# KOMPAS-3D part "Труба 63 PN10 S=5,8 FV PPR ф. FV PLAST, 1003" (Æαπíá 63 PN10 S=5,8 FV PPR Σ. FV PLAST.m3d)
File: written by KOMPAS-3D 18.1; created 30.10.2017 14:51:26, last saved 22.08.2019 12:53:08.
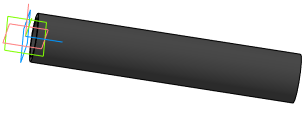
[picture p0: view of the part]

Document properties: Автор: Милов; Организация: Милов; Полное имя файла: D:\1 ПКИ 3D\Полипропиленовые фитинги, трубы\Трубы\Труба 63 PN10 S=5,8 FV PPR ф. FV PLAST.m3d

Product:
- Part/product: Труба 63 PN10 S=5,8 FV PPR ф. FV PLAST  | designation 1003
    Материал: Полипропилен  ГОСТ 26996-86 (density 900 kg/m3)
    Масса: 0.152669
    Раздел спецификации: Прочие изделия
    Примечание: м
- Part/product: Труба 63 PN10 S=5,8 FV PPR ф. FV PLAST  | designation 1002
    Материал: Полипропилен  ГОСТ 26996-86 (density 900 kg/m3)
    Масса: 0.152669
    Раздел спецификации: Прочие изделия
    Примечание: м
- Part/product: Труба 63 PN10 S=5,8 ПВХ  | designation 4
    Материал: Полипропилен  ГОСТ 26996-86 (density 900 kg/m3)
    Масса: 0.326673
    Раздел спецификации: Прочие изделия
    Примечание: м
- Part/product: Труба 63 PN10 S=5,8 FV PPR ф. FV PLAST  | designation 1000
    Материал: Полипропилен  ГОСТ 26996-86 (density 900 kg/m3)
    Масса: 0.864543
    Раздел спецификации: Прочие изделия
    Примечание: м
- Part/product: Труба 63 PN10 S=5,8 FV PPR ф. FV PLAST
    Материал: Полипропилен  ГОСТ 26996-86 (density 900 kg/m3)
    Масса: 0.152669
    Раздел спецификации: Прочие изделия
    Примечание: м
- Part/product: Труба ф63х5.8 (PN10) FV PPR ф. FV PLAST  | designation 01 (с поворотом напр.)
    Материал: Полипропилен  ГОСТ 26996-86 (density 900 kg/m3)
    Масса: 0.132262
- Part/product: Труба 63 PN10 S=5,8 FV PPR ф. FV PLAST  | designation 01
    Материал: Полипропилен  ГОСТ 26996-86 (density 900 kg/m3)
    Масса: 0.129218
    Раздел спецификации: Прочие изделия
    Примечание: м
- Part/product: Труба 63 PN10 S=5,8 FV PPR ф. FV PLAST  | designation 02
    Материал: Полипропилен  ГОСТ 26996-86 (density 900 kg/m3)
    Масса: 0.129218
    Раздел спецификации: Прочие изделия
    Примечание: м
- Part/product: Труба 63 PN10 S=5,8  | designation ПВХ
    Материал: Полипропилен  ГОСТ 26996-86 (density 900 kg/m3)
    Масса: 0.113272
    Раздел спецификации: Прочие изделия
    Примечание: м
- Part/product: Труба 63 PN10 S=5,8 ПВХ  | designation 1
    Материал: Полипропилен  ГОСТ 26996-86 (density 900 kg/m3)
    Масса: 0.0640683
    Раздел спецификации: Прочие изделия
    Примечание: м
  - Body: Тело 1
      Масса: 0.0800148
- Part/product: Труба 63 PN10 S=5,8 ПВХ  | designation 2
    Материал: Полипропилен  ГОСТ 26996-86 (density 900 kg/m3)
    Раздел спецификации: Прочие изделия
    Примечание: м
- Part/product: Труба 63 PN10 S=5,8 ПВХ  | designation 3
    Материал: Полипропилен  ГОСТ 26996-86 (density 900 kg/m3)
    Масса: 0.059608
    Раздел спецификации: Прочие изделия
    Примечание: м
- Part/product: Труба 63 PN10 S=5,8 ПВХ  | designation 5
    Материал: Полипропилен  ГОСТ 26996-86 (density 900 kg/m3)
    Масса: 0.129218
    Раздел спецификации: Прочие изделия
    Примечание: м
- Part/product: Труба 63 PN10 S=5,8 FV PPR ф. FV PLAST  | designation 1001
    Материал: Полипропилен  ГОСТ 26996-86 (density 900 kg/m3)
    Масса: 0.294541
    Раздел спецификации: Прочие изделия
    Примечание: м
- Part/product: Труба 63 PN10 S=5,8 FV PPR ф. FV PLAST  | designation М32колено
    Материал: Полипропилен  ГОСТ 26996-86 (density 900 kg/m3)
    Масса: 0.051404
    Раздел спецификации: Прочие изделия
    Примечание: м

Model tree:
1. Эскиз:1
2. Операция выдавливания:1  (with: Вырезать элемент выдавливания:8)  (labels: Полипропилен  ГОСТ 26996-86; L + 34.0)
3. Элемент выдавливания:1  (with: Операция выдавливания:1)  (labels: Полипропилен  ГОСТ 26996-86)
     Расстояние 2 = 34
4. Элемент выдавливания:2  (with: Операция выдавливания:1)
     Расстояние 2 = 30
5. Элемент выдавливания:5  (with: Операция выдавливания:1)
     Расстояние 1 = 10
6. Элемент выдавливания:6  (with: Элемент выдавливания:5)
     Расстояние 1 = 568
7. Эскиз:5  (with: Элемент выдавливания:6, Элемент выдавливания:2)  (labels: FV PPR Редукция 32х20 AA209032020; Труба 63 PN10 S=5,8 FV PPR ф. FV PLAST; FV PPR Вварное седло 63х32)
8. Элемент выдавливания:9  (labels: Полипропилен  ГОСТ 26996-86; L+32.755)
     Расстояние 2 = 91
9. Элемент выдавливания:10  (with: Операция выдавливания:1)
     Расстояние 2 = 30
10. Элемент выдавливания:11  (with: Элемент выдавливания:10)  (labels: Полипропилен  ГОСТ 26996-86; -2|L)
     Расстояние 2 = 24
11. Фаска:5  (with: Операция выдавливания:1)  (labels: Полипропилен  ГОСТ 26996-86; L+2)
     Угол = 15; Длина 1 = 3; Длина 2 = 0.803848
12. Фаска:2  (with: Операция выдавливания:1)  (labels: Полипропилен  ГОСТ 26996-86)
     Угол = 15; Длина 1 = 3; Длина 2 = 0.803848

Expressions: 63-5.8*2; L-76+32
Referenced files in D:\Magna\Магна Ins\Магна ins 40\3Д\: М40-00.15.000 - Корпус М40.a3d
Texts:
  М32колено

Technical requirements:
  Gost Type A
